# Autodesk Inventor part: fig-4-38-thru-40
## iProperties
Created: 2004-05
Part Number: fig-4-38-thru-40
Document SubType Name: Modeling
Designer: CADCIM Technologies
Manufacturer: Standard
Standards Organization: Custom
Author: CADCIM Technologies
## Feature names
1. Revolution1
2. Extrusion3
